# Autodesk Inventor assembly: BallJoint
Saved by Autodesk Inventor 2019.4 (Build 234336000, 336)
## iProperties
Created: 2020-04
Part Number: BallJoint
Document SubType Name: Assembly
Designer: Administrator
Title: BallJoint v14
Author: Administrator
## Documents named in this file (3)
- c:\worker\convert-fusion-r03\tmp\job-1\48\output\files\ccae6ef3-9f0e-42ff-b199-3a2c6474057a\BallJoint v14_3.iam
- c:\worker\convert-fusion-r03\tmp\job-1\48\output\files\ccae6ef3-9f0e-42ff-b199-3a2c6474057a\Component1_1.ipt
- c:\worker\convert-fusion-r03\tmp\job-1\48\output\files\ccae6ef3-9f0e-42ff-b199-3a2c6474057a\Component2_1.ipt
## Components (2 placed, 2 different names)
1. Component1:1
2. Component2:1
